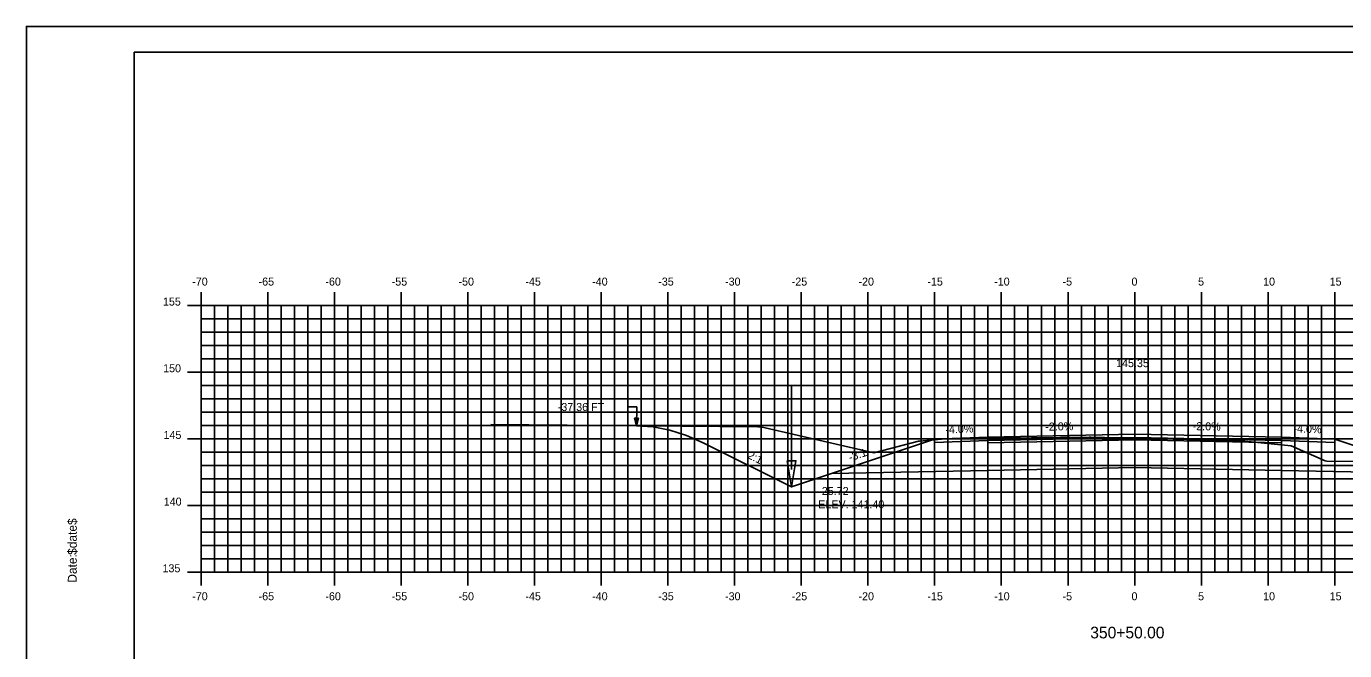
# Model space of a CAD drawing. Extents: x 1144529 to 1144699, y 608981 to 609091.
# Drawn here: x 1144528.8 to 1144627.6, y 609044.5 to 609091.3 of the extents above; entities that cross this region are included whole.
import ezdxf

# ---------------------------------------------------------------- set-up
doc = ezdxf.new("R2010")
doc.units = 0
for name, color, linetype in [('ANNOTATION', 7, 'Continuous'), ('BORDER', 7, 'Continuous'), ('D_Drainage_Ditch_Line', 7, 'Continuous'), ('D_Roadway_Centerline', 7, 'Continuous'), ('D_Roadway_Centerline_Text', 7, 'Continuous'), ('D_Roadway_Edge_Shoulder', 7, 'Continuous'), ('D_Roadway_Edge_TW', 7, 'Continuous'), ('D_Roadway_Pavement', 7, 'Continuous'), ('D_Roadway_SlopeLines', 7, 'Continuous'), ('D_Roadway_SubGrade', 7, 'Continuous'), ('D_Text_Standard', 7, 'Continuous'), ('H_V ANNOTATION', 7, 'Continuous'), ('MAJOR', 7, 'Continuous'), ('MINOR', 7, 'Continuous'), ('PLOT BOUNDARY', 7, 'Continuous'), ('S_Roadway_Centerline', 7, 'Continuous')]:
    doc.layers.add(name, color=color, linetype=linetype)

msp = doc.modelspace()

# ---------------------------------------------------------------- linework, layer by layer
msp.add_lwpolyline([(1144574.501, 609061.322), (1144575.751, 609061.235), (1144577.001, 609060.994), (1144578.251, 609060.599), (1144579.501, 609060.051), (1144586.138, 609056.732), (1144589.138, 609057.732), (1144596.861, 609060.307), (1144596.862, 609060.307), (1144600.862, 609060.467), (1144611.862, 609060.687), (1144622.862, 609060.467), (1144626.862, 609060.307), (1144634.586, 609057.732), (1144637.586, 609056.732), (1144638.331, 609057.105), (1144639.581, 609057.648), (1144640.831, 609058.025), (1144642.081, 609058.239), (1144643.331, 609058.287)])
at = {"layer": 'BORDER'}
msp.add_lwpolyline([(1144536.863, 608984.335), (1144696.863, 608984.335), (1144696.863, 609089.335), (1144536.863, 609089.335)], close=True, dxfattribs=at)
at = {"layer": 'D_Drainage_Ditch_Line'}
msp.add_line((1144586.138, 609058.045), (1144586.138, 609064.288), dxfattribs=at)
msp.add_lwpolyline([(1144585.81, 609058.701), (1144586.466, 609058.701), (1144586.138, 609056.732)], close=True, dxfattribs=at)
at = {"layer": 'D_Roadway_Edge_Shoulder'}
for points in [[(1144600.862, 609060.467), (1144596.862, 609060.307), (1144596.862, 609060.057), (1144600.862, 609060.217)], [(1144622.862, 609060.467), (1144626.862, 609060.307), (1144626.862, 609060.057), (1144622.862, 609060.217)]]:
    msp.add_lwpolyline(points, close=True, dxfattribs=at)
at = {"layer": 'D_Roadway_Edge_TW'}
msp.add_lwpolyline([(1144600.862, 609060.217), (1144600.862, 609060.467), (1144611.862, 609060.687), (1144622.862, 609060.467), (1144622.862, 609060.217), (1144611.862, 609060.437)], close=True, dxfattribs=at)
at = {"layer": 'D_Roadway_Pavement'}
msp.add_lwpolyline([(1144600.862, 609060.05), (1144600.862, 609060.217), (1144611.862, 609060.437), (1144622.862, 609060.217), (1144622.862, 609060.05), (1144611.862, 609060.27)], close=True, dxfattribs=at)
at = {"layer": 'D_Roadway_SlopeLines'}
for points in [[(1144586.138, 609056.732), (1144579.501, 609060.051), (1144578.251, 609060.599), (1144577.001, 609060.994), (1144575.751, 609061.235), (1144574.501, 609061.322)], [(1144589.138, 609057.732), (1144586.138, 609056.732)]]:
    msp.add_lwpolyline(points, dxfattribs=at)
at = {"layer": 'D_Roadway_SubGrade'}
for points in [[(1144600.862, 609060.05), (1144600.862, 609060.217), (1144596.862, 609060.057), (1144596.862, 609060.307), (1144596.861, 609060.307), (1144589.138, 609057.732), (1144600.862, 609057.967)], [(1144600.862, 609057.967), (1144600.862, 609060.05), (1144611.862, 609060.27), (1144622.862, 609060.05), (1144622.862, 609057.967), (1144611.862, 609058.187)], [(1144622.862, 609060.05), (1144622.862, 609060.217), (1144626.862, 609060.057), (1144626.862, 609060.307), (1144626.862, 609060.307), (1144634.586, 609057.732), (1144622.862, 609057.967)]]:
    msp.add_lwpolyline(points, close=True, dxfattribs=at)
at = {"layer": 'D_Text_Standard'}
msp.add_lwpolyline([(1144574.501, 609061.301), (1144574.529, 609062.732), (1144573.849, 609062.732)], dxfattribs=at)
msp.add_lwpolyline([(1144574.501, 609061.301), (1144574.367, 609061.886), (1144574.658, 609061.88)], close=True, dxfattribs=at)
at = {"layer": 'MAJOR'}
for p, q in [((1144541.862, 609071.337), (1144541.862, 609070.335)), ((1144546.862, 609071.337), (1144546.862, 609070.335)), ((1144551.862, 609071.337), (1144551.862, 609070.335)), ((1144556.862, 609071.337), (1144556.862, 609070.335)), ((1144561.862, 609071.337), (1144561.862, 609070.335)), ((1144566.862, 609071.337), (1144566.862, 609070.335)), ((1144571.862, 609071.337), (1144571.862, 609070.335)), ((1144576.862, 609071.337), (1144576.862, 609070.335)), ((1144581.862, 609071.337), (1144581.862, 609070.335)), ((1144586.862, 609071.337), (1144586.862, 609070.335)), ((1144591.862, 609071.337), (1144591.862, 609070.335)), ((1144596.862, 609071.337), (1144596.862, 609070.335)), ((1144601.862, 609071.337), (1144601.862, 609070.335)), ((1144606.862, 609071.337), (1144606.862, 609070.335)), ((1144611.862, 609071.337), (1144611.862, 609070.335)), ((1144616.862, 609071.337), (1144616.862, 609070.335)), ((1144621.862, 609071.337), (1144621.862, 609070.335)), ((1144626.862, 609071.337), (1144626.862, 609070.335)), ((1144540.86, 609070.335), (1144541.862, 609070.335)), ((1144541.862, 609070.335), (1144681.862, 609070.335)), ((1144541.862, 609050.335), (1144541.862, 609070.335)), ((1144541.862, 609050.335), (1144541.862, 609070.335)), ((1144541.862, 609070.335), (1144681.862, 609070.335)), ((1144546.862, 609050.335), (1144546.862, 609070.335)), ((1144551.862, 609050.335), (1144551.862, 609070.335)), ((1144556.862, 609050.335), (1144556.862, 609070.335)), ((1144561.862, 609050.335), (1144561.862, 609070.335)), ((1144566.862, 609050.335), (1144566.862, 609070.335)), ((1144571.862, 609050.335), (1144571.862, 609070.335)), ((1144576.862, 609050.335), (1144576.862, 609070.335)), ((1144581.862, 609050.335), (1144581.862, 609070.335)), ((1144586.862, 609050.335), (1144586.862, 609070.335)), ((1144591.862, 609050.335), (1144591.862, 609070.335)), ((1144596.862, 609050.335), (1144596.862, 609070.335)), ((1144601.862, 609050.335), (1144601.862, 609070.335)), ((1144606.862, 609050.335), (1144606.862, 609070.335)), ((1144611.862, 609050.335), (1144611.862, 609070.335)), ((1144616.862, 609050.335), (1144616.862, 609070.335)), ((1144621.862, 609050.335), (1144621.862, 609070.335)), ((1144626.862, 609050.335), (1144626.862, 609070.335)), ((1144540.86, 609065.335), (1144541.862, 609065.335)), ((1144541.862, 609065.335), (1144681.862, 609065.335)), ((1144540.86, 609060.335), (1144541.862, 609060.335)), ((1144541.862, 609060.335), (1144681.862, 609060.335)), ((1144540.86, 609055.335), (1144541.862, 609055.335)), ((1144541.862, 609055.335), (1144681.862, 609055.335)), ((1144540.86, 609050.335), (1144541.862, 609050.335)), ((1144541.862, 609050.335), (1144681.862, 609050.335)), ((1144541.862, 609050.335), (1144681.862, 609050.335)), ((1144541.862, 609049.333), (1144541.862, 609050.335)), ((1144546.862, 609049.333), (1144546.862, 609050.335)), ((1144551.862, 609049.333), (1144551.862, 609050.335)), ((1144556.862, 609049.333), (1144556.862, 609050.335)), ((1144561.862, 609049.333), (1144561.862, 609050.335)), ((1144566.862, 609049.333), (1144566.862, 609050.335)), ((1144571.862, 609049.333), (1144571.862, 609050.335)), ((1144576.862, 609049.333), (1144576.862, 609050.335)), ((1144581.862, 609049.333), (1144581.862, 609050.335)), ((1144586.862, 609049.333), (1144586.862, 609050.335)), ((1144591.862, 609049.333), (1144591.862, 609050.335)), ((1144596.862, 609049.333), (1144596.862, 609050.335)), ((1144601.862, 609049.333), (1144601.862, 609050.335)), ((1144606.862, 609049.333), (1144606.862, 609050.335)), ((1144611.862, 609049.333), (1144611.862, 609050.335)), ((1144616.862, 609049.333), (1144616.862, 609050.335)), ((1144621.862, 609049.333), (1144621.862, 609050.335)), ((1144626.862, 609049.333), (1144626.862, 609050.335))]:
    msp.add_line(p, q, dxfattribs=at)
at = {"layer": 'MINOR'}
for p, q in [((1144542.862, 609050.335), (1144542.862, 609070.335)), ((1144543.862, 609050.335), (1144543.862, 609070.335)), ((1144544.862, 609050.335), (1144544.862, 609070.335)), ((1144545.862, 609050.335), (1144545.862, 609070.335)), ((1144547.862, 609050.335), (1144547.862, 609070.335)), ((1144548.862, 609050.335), (1144548.862, 609070.335)), ((1144549.862, 609050.335), (1144549.862, 609070.335)), ((1144550.862, 609050.335), (1144550.862, 609070.335)), ((1144552.862, 609050.335), (1144552.862, 609070.335)), ((1144553.862, 609050.335), (1144553.862, 609070.335)), ((1144554.862, 609050.335), (1144554.862, 609070.335)), ((1144555.862, 609050.335), (1144555.862, 609070.335)), ((1144557.862, 609050.335), (1144557.862, 609070.335)), ((1144558.862, 609050.335), (1144558.862, 609070.335)), ((1144559.862, 609050.335), (1144559.862, 609070.335)), ((1144560.862, 609050.335), (1144560.862, 609070.335)), ((1144562.862, 609050.335), (1144562.862, 609070.335)), ((1144563.862, 609050.335), (1144563.862, 609070.335)), ((1144564.862, 609050.335), (1144564.862, 609070.335)), ((1144565.862, 609050.335), (1144565.862, 609070.335)), ((1144567.862, 609050.335), (1144567.862, 609070.335)), ((1144568.862, 609050.335), (1144568.862, 609070.335)), ((1144569.862, 609050.335), (1144569.862, 609070.335)), ((1144570.862, 609050.335), (1144570.862, 609070.335)), ((1144572.862, 609050.335), (1144572.862, 609070.335)), ((1144573.862, 609050.335), (1144573.862, 609070.335)), ((1144574.862, 609050.335), (1144574.862, 609070.335)), ((1144575.862, 609050.335), (1144575.862, 609070.335)), ((1144577.862, 609050.335), (1144577.862, 609070.335)), ((1144578.862, 609050.335), (1144578.862, 609070.335)), ((1144579.862, 609050.335), (1144579.862, 609070.335)), ((1144580.862, 609050.335), (1144580.862, 609070.335)), ((1144582.862, 609050.335), (1144582.862, 609070.335)), ((1144583.862, 609050.335), (1144583.862, 609070.335)), ((1144584.862, 609050.335), (1144584.862, 609070.335)), ((1144585.862, 609050.335), (1144585.862, 609070.335)), ((1144587.862, 609050.335), (1144587.862, 609070.335)), ((1144588.862, 609050.335), (1144588.862, 609070.335)), ((1144589.862, 609050.335), (1144589.862, 609070.335)), ((1144590.862, 609050.335), (1144590.862, 609070.335)), ((1144592.862, 609050.335), (1144592.862, 609070.335)), ((1144593.862, 609050.335), (1144593.862, 609070.335)), ((1144594.862, 609050.335), (1144594.862, 609070.335)), ((1144595.862, 609050.335), (1144595.862, 609070.335)), ((1144597.862, 609050.335), (1144597.862, 609070.335)), ((1144598.862, 609050.335), (1144598.862, 609070.335)), ((1144599.862, 609050.335), (1144599.862, 609070.335)), ((1144600.862, 609050.335), (1144600.862, 609070.335)), ((1144602.862, 609050.335), (1144602.862, 609070.335)), ((1144603.862, 609050.335), (1144603.862, 609070.335)), ((1144604.862, 609050.335), (1144604.862, 609070.335)), ((1144605.862, 609050.335), (1144605.862, 609070.335)), ((1144607.862, 609050.335), (1144607.862, 609070.335)), ((1144608.862, 609050.335), (1144608.862, 609070.335)), ((1144609.862, 609050.335), (1144609.862, 609070.335)), ((1144610.862, 609050.335), (1144610.862, 609070.335)), ((1144612.862, 609050.335), (1144612.862, 609070.335)), ((1144613.862, 609050.335), (1144613.862, 609070.335)), ((1144614.862, 609050.335), (1144614.862, 609070.335)), ((1144615.862, 609050.335), (1144615.862, 609070.335)), ((1144617.862, 609050.335), (1144617.862, 609070.335)), ((1144618.862, 609050.335), (1144618.862, 609070.335)), ((1144619.862, 609050.335), (1144619.862, 609070.335)), ((1144620.862, 609050.335), (1144620.862, 609070.335)), ((1144622.862, 609050.335), (1144622.862, 609070.335)), ((1144623.862, 609050.335), (1144623.862, 609070.335)), ((1144624.862, 609050.335), (1144624.862, 609070.335)), ((1144625.862, 609050.335), (1144625.862, 609070.335)), ((1144541.862, 609069.335), (1144681.862, 609069.335)), ((1144541.862, 609069.335), (1144542.864, 609069.335)), ((1144541.862, 609068.335), (1144681.862, 609068.335)), ((1144541.862, 609068.335), (1144542.864, 609068.335)), ((1144541.862, 609067.335), (1144681.862, 609067.335)), ((1144541.862, 609067.335), (1144542.864, 609067.335)), ((1144541.862, 609066.335), (1144681.862, 609066.335)), ((1144541.862, 609066.335), (1144542.864, 609066.335)), ((1144541.862, 609064.335), (1144681.862, 609064.335)), ((1144541.862, 609064.335), (1144542.864, 609064.335)), ((1144541.862, 609063.335), (1144681.862, 609063.335)), ((1144541.862, 609063.335), (1144542.864, 609063.335)), ((1144541.862, 609062.335), (1144681.862, 609062.335)), ((1144541.862, 609062.335), (1144542.864, 609062.335)), ((1144541.862, 609061.335), (1144681.862, 609061.335)), ((1144541.862, 609061.335), (1144542.864, 609061.335)), ((1144541.862, 609059.335), (1144681.862, 609059.335)), ((1144541.862, 609059.335), (1144542.864, 609059.335)), ((1144541.862, 609058.335), (1144681.862, 609058.335)), ((1144541.862, 609058.335), (1144542.864, 609058.335)), ((1144541.862, 609057.335), (1144681.862, 609057.335)), ((1144541.862, 609057.335), (1144542.864, 609057.335)), ((1144541.862, 609056.335), (1144681.862, 609056.335)), ((1144541.862, 609056.335), (1144542.864, 609056.335)), ((1144541.862, 609054.335), (1144681.862, 609054.335)), ((1144541.862, 609054.335), (1144542.864, 609054.335)), ((1144541.862, 609053.335), (1144681.862, 609053.335)), ((1144541.862, 609053.335), (1144542.864, 609053.335)), ((1144541.862, 609052.335), (1144681.862, 609052.335)), ((1144541.862, 609052.335), (1144542.864, 609052.335)), ((1144541.862, 609051.335), (1144681.862, 609051.335)), ((1144541.862, 609051.335), (1144542.864, 609051.335))]:
    msp.add_line(p, q, dxfattribs=at)
at = {"layer": 'PLOT BOUNDARY'}
msp.add_lwpolyline([(1144528.769, 608981.276), (1144698.769, 608981.276), (1144698.769, 609091.276), (1144528.769, 609091.276)], close=True, dxfattribs=at)
at = {"layer": 'S_Roadway_Centerline'}
msp.add_lwpolyline([(1144563.592, 609061.416), (1144583.607, 609061.244), (1144583.773, 609061.241), (1144583.821, 609061.236), (1144592.307, 609059.29), (1144592.395, 609059.316), (1144595.656, 609060.163), (1144595.718, 609060.167), (1144597.643, 609060.351), (1144608.46, 609060.473), (1144608.57, 609060.475), (1144619.886, 609060.185), (1144620.036, 609060.18), (1144620.097, 609060.175), (1144623.583, 609059.807), (1144626.132, 609058.695), (1144626.261, 609058.67), (1144631.25, 609058.646), (1144631.393, 609058.672), (1144633.073, 609058.566), (1144661.744, 609057.785)], dxfattribs=at)

# ---------------------------------------------------------------- texts
at = {"layer": 'ANNOTATION'}
for s, rotation, p in [('-4.0%', 2.29061, (1144597.678, 609060.74)), ('-2.0%', 1.14576, (1144605.165, 609060.953)), ('-2.0%', 358.85424, (1144616.205, 609061)), ('-4.0%', 357.70939, (1144623.758, 609060.832)), ('2:1', 333.43495, (1144582.786, 609058.926)), ('-3:1', 18.43482, (1144590.517, 609058.646))]:
    msp.add_text(s, height=0.6, rotation=rotation, dxfattribs=at).set_placement(p)
at = {"layer": 'BORDER'}
for s, p in [('$date$', (1144532.547, 609051.64)), ('Date:', (1144532.547, 609049.552))]:
    msp.add_text(s, height=0.6696, rotation=90, dxfattribs=at).set_placement(p)
at = {"layer": 'D_Roadway_Centerline'}
for s, p in [('C', (1144611.857, 609060.687)), ('L', (1144611.862, 609060.68))]:
    msp.add_text(s, height=0.0146, dxfattribs=at).set_placement(p)
at = {"layer": 'D_Roadway_Centerline_Text'}
msp.add_text('145.35', height=0.6, dxfattribs=at).set_placement((1144610.468, 609065.719))
at = {"layer": 'D_Text_Standard'}
for s, p in [('-37.36 FT', (1144568.609, 609062.432)), ('-25.72', (1144588.138, 609056.132)), ('ELEV. 141.40', (1144588.138, 609055.13))]:
    msp.add_text(s, height=0.6, dxfattribs=at).set_placement(p)
at = {"layer": 'H_V ANNOTATION'}
for s, height, p in [('-70', 0.6, (1144541.204, 609071.835)), ('-65', 0.6, (1144546.18, 609071.835)), ('-60', 0.6, (1144551.188, 609071.835)), ('-55', 0.6, (1144556.158, 609071.835)), ('-50', 0.6, (1144561.167, 609071.835)), ('-45', 0.6, (1144566.18, 609071.835)), ('-40', 0.6, (1144571.188, 609071.835)), ('-35', 0.6, (1144576.143, 609071.835)), ('-30', 0.6, (1144581.151, 609071.835)), ('-25', 0.6, (1144586.148, 609071.835)), ('-20', 0.6, (1144591.156, 609071.835)), ('-15', 0.6, (1144596.319, 609071.835)), ('-10', 0.6, (1144601.327, 609071.835)), ('-5', 0.6, (1144606.453, 609071.835)), ('0', 0.6, (1144611.621, 609071.835)), ('5', 0.6, (1144616.613, 609071.835)), ('10', 0.6, (1144621.488, 609071.835)), ('15', 0.6, (1144626.48, 609071.835)), ('155', 0.6, (1144539.008, 609070.335)), ('150', 0.6, (1144539.024, 609065.335)), ('145', 0.6, (1144539.051, 609060.335)), ('140', 0.6, (1144539.067, 609055.335)), ('135', 0.6, (1144538.976, 609050.335)), ('-70', 0.6, (1144541.204, 609048.235)), ('-65', 0.6, (1144546.18, 609048.235)), ('-60', 0.6, (1144551.188, 609048.235)), ('-55', 0.6, (1144556.158, 609048.235)), ('-50', 0.6, (1144561.167, 609048.235)), ('-45', 0.6, (1144566.18, 609048.235)), ('-40', 0.6, (1144571.188, 609048.235)), ('-35', 0.6, (1144576.143, 609048.235)), ('-30', 0.6, (1144581.151, 609048.235)), ('-25', 0.6, (1144586.148, 609048.235)), ('-20', 0.6, (1144591.156, 609048.235)), ('-15', 0.6, (1144596.319, 609048.235)), ('-10', 0.6, (1144601.327, 609048.235)), ('-5', 0.6, (1144606.453, 609048.235)), ('0', 0.6, (1144611.621, 609048.235)), ('5', 0.6, (1144616.613, 609048.235)), ('10', 0.6, (1144621.488, 609048.235)), ('15', 0.6, (1144626.48, 609048.235)), ('350+50.00', 0.875, (1144608.53, 609045.378))]:
    msp.add_text(s, height=height, dxfattribs=at).set_placement(p)
at = {"layer": 'MAJOR'}
msp.add_text('-', height=0.006, dxfattribs=at).set_placement((1144541.858, 609050.335))
at = {"layer": 'S_Roadway_Centerline'}
for s, p in [('L', (1144608.562, 609060.468)), ('C', (1144608.565, 609060.475))]:
    msp.add_text(s, height=0.0146, dxfattribs=at).set_placement(p)

doc.saveas('drawing.dxf')
